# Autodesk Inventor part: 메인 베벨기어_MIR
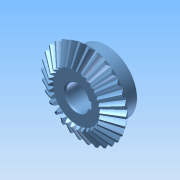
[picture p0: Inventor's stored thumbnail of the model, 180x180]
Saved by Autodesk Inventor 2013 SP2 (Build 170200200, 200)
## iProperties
Created: 2026-07
Part Number: 메인 베벨기어_MIR
Material: Generic
Document SubType Name: Modeling
Designer: aa
Density: 1 g/cm^3
Author: aa
변환 표준: STEP AP214IS
전처리기: Build: 200, Release: 2013 SP2 Update 6 - Date: Thu 07/17/2014
전송 단위: 밀리미터
불확실성: 0.01
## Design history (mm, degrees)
derived "메인 베벨기어.ipt"
feature "Solid1::메인 베벨기어.ipt" dims "d0" = 10
tag "피쳐 태그1"
node "솔리드1"
